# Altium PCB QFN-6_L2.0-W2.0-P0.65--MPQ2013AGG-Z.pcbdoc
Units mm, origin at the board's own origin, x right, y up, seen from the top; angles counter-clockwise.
Board outline 15.34 x 14.92 mm, 2 copper layers (Top Layer, Bottom Layer), stack 0 mm thick; 1 components, 0 nets, 7 pads, 0 vias.
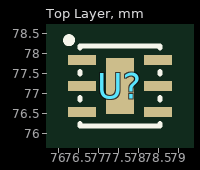
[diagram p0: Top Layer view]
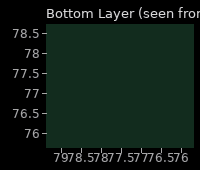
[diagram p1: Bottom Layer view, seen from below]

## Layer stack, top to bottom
Top Layer: signal copper (thickness not stored)
Bottom Layer: signal copper (thickness not stored)

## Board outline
85.195,69.85 69.85,69.85 69.85,84.768 85.195,84.768

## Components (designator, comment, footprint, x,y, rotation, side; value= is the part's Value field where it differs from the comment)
U? "" QFN-6_L2.0-W2.0-P0.65--MPQ2013AGG-Z 77.545,77.2 r0 top

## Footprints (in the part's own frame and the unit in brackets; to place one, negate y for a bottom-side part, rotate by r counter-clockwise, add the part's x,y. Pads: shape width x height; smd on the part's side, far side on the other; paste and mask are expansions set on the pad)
QFN-6_L2.0-W2.0-P0.65--MPQ2013AGG-Z [mm]
  rect 0.7x0.25 smd: 1(-0.95,0.65) 2(-0.95,0) 3(-0.95,-0.65) 4(0.95,-0.65) 5(0.95,0) 6(0.95,0.65)
  rect 0.7x1.4 smd: 7(0,0)
  silkscreen extent -1.34,-1 1,1.22

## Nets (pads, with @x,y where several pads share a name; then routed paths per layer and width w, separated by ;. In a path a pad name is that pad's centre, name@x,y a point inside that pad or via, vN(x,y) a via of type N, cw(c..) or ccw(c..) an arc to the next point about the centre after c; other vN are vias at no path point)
pads on no net: U?.1 U?.2 U?.3 U?.4 U?.5 U?.6 U?.7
